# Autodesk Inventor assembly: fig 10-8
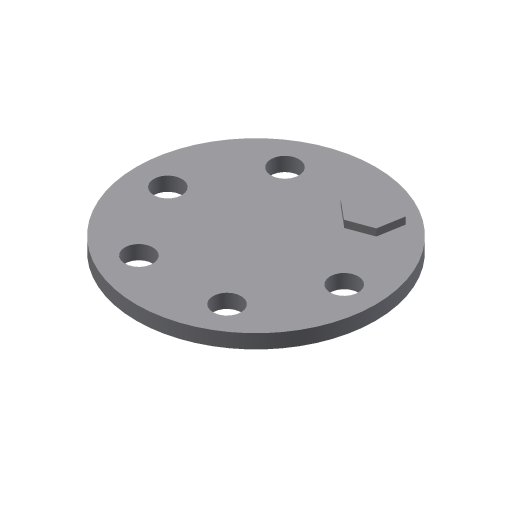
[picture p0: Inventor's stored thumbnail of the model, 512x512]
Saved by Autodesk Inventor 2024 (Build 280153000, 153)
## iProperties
Created: 2008-05
Part Number: fig 10-8
Document SubType Name: Assembly
Designer: CADCIM
Author: CADCIM
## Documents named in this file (3)
- D:\PROJECTS\Project 2023\RESOURCES INVENTOR 2024\RESOURCES INVENTOR 2024\Inventor_2023_Part\Inventor_2024_Part\c10_Inv_2024_prt\fig 10-8.iam
- D:\PROJECTS\Project 2023\RESOURCES INVENTOR 2024\RESOURCES INVENTOR 2024\Inventor_2023_Part\Inventor_2024_Part\c10_Inv_2024_prt\Part4.ipt
- D:\PROJECTS\Project 2023\RESOURCES INVENTOR 2024\RESOURCES INVENTOR 2024\Inventor_2023_Part\Inventor_2024_Part\c10_Inv_2024_prt\Part5.ipt
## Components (2 placed, 2 different names)
1. Part4:1 — Insert:1
2. Part5:1 — Insert:1
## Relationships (1: Insert 1)
- Insert:1: Part4:1 ↔ Part5:1
